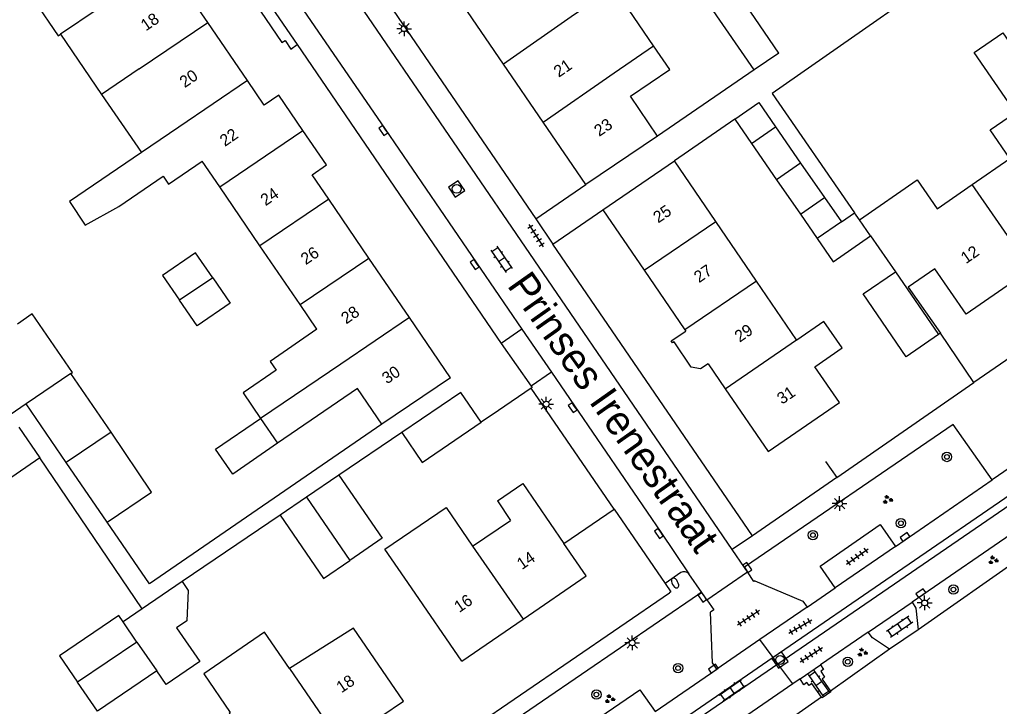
# Model space of a CAD drawing. Extents: x 137999 to 141000, y 397500 to 400501.
# Drawn here: x 138055 to 138138.3, y 399810.1 to 399868.5 of the extents above; entities that cross this region are included whole.
import ezdxf

# ---------------------------------------------------------------- set-up
doc = ezdxf.new("R2010")
doc.units = 0
for name, color, linetype in [('gg-afsc-erfafscheiding', 7, 'Continuous'), ('gg-afsc-muur', 7, 'Continuous'), ('gg-anno-huisnummerreeks BGT', 7, 'Continuous'), ('gg-anno-openbare ruimte label', 7, 'Continuous'), ('gg-bbg-bijgebouw', 7, 'Continuous'), ('gg-bbg-gedigitaliseerde bebouwing', 7, 'Continuous'), ('gg-bbg-gedigitaliseerde bijgebouw', 7, 'Continuous'), ('gg-bbg-hoofdgebouw', 7, 'Continuous'), ('gg-bbg-luifel en loopbrug', 7, 'Continuous'), ('gg-bbg-tussenscheiding', 7, 'Continuous'), ('gg-knt-verharding', 7, 'Continuous'), ('gg-knt-verharding nz', 7, 'Continuous'), ('gt-grn-weggrens', 7, 'Continuous'), ('gt-symb-boom', 7, 'Continuous'), ('gt-symb-brandkraan', 7, 'Continuous'), ('gt-symb-groenvak', 7, 'Continuous'), ('gt-symb-klinker verharding', 7, 'Continuous'), ('gt-symb-kolk', 7, 'Continuous'), ('gt-symb-lichtmast', 7, 'Continuous'), ('gt-symb-rioolschacht', 7, 'Continuous'), ('gt-symb-tegel verharding', 7, 'Continuous')]:
    doc.layers.add(name, color=color, linetype=linetype)

# ---------------------------------------------------------------- blocks, each defined once
blk = doc.blocks.new('gt0-KL1')
at = {"layer": 'gt-symb-klinker verharding'}
for p, q in [((-1.15, 0.3), (1.15, 0.3)), ((-1, -0.3), (-1, 0.3)), ((-0.5, 0.3), (-0.5, 0.45)), ((0, -0.3), (0, 0.3)), ((0.5, 0.3), (0.5, 0.45)), ((1, -0.3), (1, 0.3)), ((-1.15, -0.3), (1.15, -0.3)), ((-0.5, -0.45), (-0.5, -0.3)), ((0.5, -0.45), (0.5, -0.3))]:
    blk.add_line(p, q, dxfattribs=at)
blk = doc.blocks.new('gt0-KOLK')
at = {"layer": 'gt-symb-kolk'}
blk.add_lwpolyline([(0, 0), (0.375, 0), (0.375, 0.4), (-0.375, 0.4), (-0.375, 0), (0, 0)], dxfattribs=at)
blk = doc.blocks.new('gt0-BOOM')
at = {"layer": 'gt-symb-boom'}
for radius in [0.4, 0.2]:
    blk.add_circle((0, 0), radius, dxfattribs=at)
blk = doc.blocks.new('gt0-RS')
at = {"layer": 'gt-symb-rioolschacht'}
blk.add_lwpolyline([(-0.5, -0.5), (0.5, -0.5), (0.5, 0.5), (-0.5, 0.5)], close=True, dxfattribs=at)
blk.add_circle((0, 0), 0.375, dxfattribs=at)
blk = doc.blocks.new('gt0-TEG1')
at = {"layer": 'gt-symb-tegel verharding'}
for p, q in [((-1.125, 0), (1.125, 0)), ((-0.9, -0.25), (-0.9, 0.25)), ((-0.45, -0.25), (-0.45, 0.25)), ((0, -0.25), (0, 0.25)), ((0.45, -0.25), (0.45, 0.25)), ((0.9, -0.25), (0.9, 0.25))]:
    blk.add_line(p, q, dxfattribs=at)
blk = doc.blocks.new('gt0-GRVAK')
at = {"layer": 'gt-symb-groenvak'}
for p, q in [((-0.11, 0.189), (-0.228, 0.24)), ((-0.182, 0.153), (0.088, 0.153)), ((-0.091, 0.211), (-0.156, 0.322)), ((-0.047, 0.214), (-0.047, 0.393)), ((-0.004, 0.211), (0.061, 0.322)), ((0.015, 0.189), (0.133, 0.24)), ((0.262, -0.052), (0.197, 0.059)), ((0.305, -0.049), (0.305, 0.13)), ((0.349, -0.052), (0.414, 0.059)), ((-0.245, -0.228), (-0.363, -0.177)), ((-0.318, -0.264), (-0.047, -0.264)), ((-0.226, -0.206), (-0.291, -0.095)), ((-0.183, -0.203), (-0.183, -0.024)), ((-0.139, -0.206), (-0.074, -0.095)), ((-0.12, -0.228), (-0.002, -0.177)), ((0.243, -0.074), (0.125, -0.023)), ((0.17, -0.11), (0.441, -0.11)), ((0.368, -0.074), (0.486, -0.023))]:
    blk.add_line(p, q, dxfattribs=at)
blk = doc.blocks.new('gt0-LMAST')
at = {"layer": 'gt-symb-lichtmast'}
for p, q in [((-0.182, 0.173), (-0.447, 0.438)), ((-0.005, 0.246), (-0.005, 0.621)), ((0.172, 0.173), (0.437, 0.438)), ((-0.255, -0.004), (-0.63, -0.004)), ((-0.182, -0.181), (-0.447, -0.446)), ((-0.005, -0.254), (-0.005, -0.629)), ((0.437, -0.446), (0.172, -0.181)), ((0.245, -0.004), (0.62, -0.004))]:
    blk.add_line(p, q, dxfattribs=at)
blk.add_circle((-0.005, -0.004), 0.25, dxfattribs=at)
blk = doc.blocks.new('gt0-BR')
at = {"layer": 'gt-symb-brandkraan'}
for centre, radius, start, end in [((-0.244, 0), 0.206, 107.56694, 252.43307), ((0.599, -2.664), 3, 106.89205, 107.56694), ((0, -0.691), 0.938, 73.10799, 106.89205), ((-0.599, -2.664), 3, 72.43309, 73.10799), ((0.244, 0), 0.206, 287.56695, 72.43309), ((0.599, 2.664), 3, 252.43307, 253.10797), ((0, 0.691), 0.938, 253.10797, 286.89206), ((-0.599, 2.664), 3, 286.89206, 287.56695)]:
    blk.add_arc(centre, radius, start, end, dxfattribs=at)

msp = doc.modelspace()

# ---------------------------------------------------------------- linework, layer by layer
at = {"layer": 'gg-afsc-erfafscheiding'}
for p, q in [((138095.747, 399835.23), (138094.268, 399834.222)), ((138087.523, 399833.339), (138082.171, 399829.72)), ((138065.463, 399818.364), (138056.772, 399831.202)), ((138147.857, 399828.129), (138131.391, 399816.568)), ((138077.181, 399826.329), (138068.857, 399820.671)), ((138128.967, 399814.919), (138123.938, 399811.369))]:
    msp.add_line(p, q, dxfattribs=at)
for points in [[(138137.989, 399875.474), (138118.988, 399862.166), (138125.991, 399852.029)], [(138085.829, 399834.047), (138066.081, 399820.493), (138062.488, 399825.728)], [(138123.19, 399810.846), (138110.856, 399802.204), (138129.838, 399773.855)]]:
    msp.add_lwpolyline(points, dxfattribs=at)
at = {"layer": 'gg-afsc-muur'}
for p, q in [((138117.464, 399864.178), (138109.256, 399858.554)), ((138115.809, 399859.981), (138110.68, 399856.441)), ((138136.135, 399837.595), (138133.3, 399841.79)), ((138098.518, 399837.118), (138095.747, 399835.23)), ((138105.58, 399826.833), (138098.518, 399837.118)), ((138124.498, 399829.524), (138136.135, 399837.595)), ((138123.535, 399830.877), (138124.498, 399829.524)), ((138101.302, 399823.917), (138105.58, 399826.833))]:
    msp.add_line(p, q, dxfattribs=at)
at = {"layer": 'gg-bbg-bijgebouw'}
for p, q in [((138119.558, 399865.612), (138117.464, 399864.178)), ((138115.809, 399859.981), (138117.866, 399861.392)), ((138133.133, 399841.676), (138130.37, 399839.79))]:
    msp.add_line(p, q, dxfattribs=at)
for points in [[(138094.268, 399834.222), (138092.535, 399836.761), (138087.523, 399833.339)], [(138087.523, 399833.339), (138089.254, 399830.804), (138094.268, 399834.222)]]:
    msp.add_lwpolyline(points, dxfattribs=at)
at = {"layer": 'gg-bbg-gedigitaliseerde bebouwing'}
for p, q in [((138058.508, 399867.203), (138062.011, 399862.099)), ((138062.011, 399862.099), (138065.406, 399857.153)), ((138109.256, 399858.554), (138106.946, 399861.936)), ((138072.05, 399854.233), (138070.551, 399856.43)), ((138114.204, 399851.275), (138110.68, 399856.441)), ((138075.466, 399849.228), (138072.05, 399854.233)), ((138117.664, 399846.204), (138114.204, 399851.275)), ((138078.879, 399844.228), (138075.466, 399849.228)), ((138121.057, 399841.231), (138117.664, 399846.204)), ((138080.313, 399842.128), (138078.879, 399844.228)), ((138123.39, 399842.78), (138121.078, 399841.2)), ((138121.078, 399841.2), (138121.057, 399841.231)), ((138083.752, 399837.09), (138076.971, 399832.436)), ((138085.829, 399834.047), (138083.752, 399837.09)), ((138075.52, 399834.55), (138076.971, 399832.436)), ((138095.64, 399827.53), (138096.767, 399825.878)), ((138093.541, 399823.68), (138096.767, 399825.878)), ((138092.61, 399813.9), (138088.34, 399820.136)), ((138075.854, 399816.375), (138070.685, 399812.828)), ((138077.974, 399813.286), (138075.854, 399816.375)), ((138083.417, 399816.727), (138077.974, 399813.286))]:
    msp.add_line(p, q, dxfattribs=at)
for points in [[(138059.684, 399872.35), (138056.301, 399870.028), (138058.324, 399867.08), (138058.508, 399867.203)], [(138108.923, 399866.216), (138105.558, 399871.16), (138102.209, 399868.88)], [(138137.521, 399859.073), (138139.684, 399860.569), (138136.172, 399865.647), (138138.597, 399867.325), (138142.11, 399862.246)], [(138106.946, 399861.936), (138110.288, 399864.211), (138108.923, 399866.216)], [(138135.986, 399854.428), (138139.197, 399856.649), (138137.521, 399859.073)], [(138065.406, 399857.153), (138059.269, 399852.977), (138060.623, 399850.988), (138063.473, 399852.57), (138067.229, 399855.148), (138067.695, 399854.47), (138070.551, 399856.43)], [(138126.408, 399851.426), (138131.313, 399854.818), (138133.007, 399852.368), (138135.986, 399854.428)], [(138080.313, 399842.128), (138076.337, 399839.399), (138076.846, 399838.658), (138074.028, 399836.724), (138075.52, 399834.55)], [(138088.34, 399820.136), (138086.084, 399823.431), (138091.278, 399826.986), (138093.541, 399823.68)]]:
    msp.add_lwpolyline(points, dxfattribs=at)
at = {"layer": 'gg-bbg-gedigitaliseerde bijgebouw'}
for p, q in [((138119.558, 399865.612), (138115.845, 399871.05)), ((138117.464, 399864.178), (138113.727, 399869.583)), ((138117.866, 399861.392), (138119.282, 399859.344)), ((138115.809, 399859.981), (138117.231, 399857.925)), ((138117.231, 399857.925), (138119.282, 399859.344)), ((138121.39, 399851.911), (138123.441, 399853.329)), ((138123.441, 399853.329), (138124.874, 399851.256)), ((138121.39, 399851.911), (138122.812, 399849.855)), ((138124.874, 399851.256), (138125.991, 399852.029)), ((138126.408, 399851.426), (138125.991, 399852.029)), ((138127.358, 399850.059), (138129.468, 399847.008)), ((138062.818, 399833.373), (138059.407, 399838.361)), ((138055.593, 399835.775), (138054.249, 399834.865)), ((138059.008, 399830.798), (138055.593, 399835.775)), ((138054.971, 399833.803), (138056.772, 399831.202)), ((138062.488, 399825.728), (138059.008, 399830.798)), ((138082.171, 399829.72), (138079.422, 399827.852)), ((138079.422, 399827.852), (138077.181, 399826.329)), ((138068.857, 399820.671), (138065.463, 399818.364)), ((138065.463, 399818.364), (138063.836, 399817.258))]:
    msp.add_line(p, q, dxfattribs=at)
for points in [[(138122.812, 399849.855), (138124.187, 399847.866), (138127.358, 399850.059)], [(138071.455, 399846.513), (138070.001, 399848.631), (138067.183, 399846.697), (138068.624, 399844.596)], [(138130.37, 399839.79), (138126.722, 399845.133), (138129.468, 399847.008)], [(138071.455, 399846.513), (138072.944, 399844.343), (138070.126, 399842.409), (138068.624, 399844.596)], [(138059.407, 399838.361), (138059.537, 399838.451), (138056.123, 399843.425), (138054.868, 399842.563)], [(138062.488, 399825.728), (138066.264, 399828.284), (138062.818, 399833.373)], [(138056.772, 399831.202), (138051.878, 399827.843), (138050.096, 399830.438)], [(138082.171, 399829.72), (138085.854, 399824.355), (138083.098, 399822.464)], [(138077.181, 399826.329), (138080.879, 399820.941), (138083.098, 399822.464)], [(138068.857, 399820.671), (138069.366, 399819.929), (138069.246, 399817.333), (138068.387, 399816.744), (138070.349, 399813.884), (138067.49, 399811.922), (138066.697, 399813.077)], [(138063.836, 399817.258), (138063.478, 399817.784), (138058.447, 399814.365), (138059.964, 399812.132)], [(138066.697, 399813.077), (138061.653, 399809.648), (138059.964, 399812.132)]]:
    msp.add_lwpolyline(points, dxfattribs=at)
at = {"layer": 'gg-bbg-hoofdgebouw'}
for p, q in [((138071.039, 399868.2), (138067.562, 399873.288)), ((138096.167, 399864.666), (138092.743, 399869.689)), ((138074.403, 399863.277), (138071.039, 399868.2)), ((138099.522, 399859.743), (138096.167, 399864.666)), ((138103.15, 399854.42), (138099.522, 399859.743)), ((138109.256, 399858.554), (138103.15, 399854.42)), ((138104.6, 399852.29), (138110.68, 399856.441)), ((138084.724, 399848.179), (138081.314, 399853.187)), ((138104.6, 399852.29), (138108.111, 399847.15)), ((138088.171, 399843.116), (138084.724, 399848.179)), ((138108.111, 399847.15), (138111.581, 399842.07)), ((138091.653, 399838.002), (138088.171, 399843.116)), ((138111.581, 399842.07), (138111.647, 399841.974)), ((138133.3, 399841.79), (138133.133, 399841.676)), ((138113.546, 399839.192), (138114.991, 399837.076)), ((138091.653, 399838.002), (138085.829, 399834.047)), ((138092.61, 399813.9), (138097.825, 399817.47))]:
    msp.add_line(p, q, dxfattribs=at)
for points in [[(138079.122, 399859.032), (138077.073, 399862.028), (138075.835, 399861.181), (138074.403, 399863.277)], [(138081.314, 399853.187), (138079.897, 399855.269), (138081.13, 399856.097), (138079.122, 399859.032)], [(138140.985, 399847.215), (138135.48, 399843.41), (138132.81, 399847.27), (138130.54, 399845.7), (138133.3, 399841.79)], [(138114.991, 399837.076), (138118.65, 399831.72), (138124.72, 399835.91), (138122.63, 399838.94), (138124.94, 399840.54), (138123.39, 399842.78)], [(138113.546, 399839.192), (138112.9, 399838.764), (138112.109, 399838.915), (138110.656, 399841.053), (138110.525, 399840.966), (138110.414, 399841.132), (138111.647, 399841.974)], [(138095.64, 399827.53), (138097.81, 399829.01), (138101.302, 399823.917)], [(138097.825, 399817.47), (138103.2, 399821.15), (138101.302, 399823.917)], [(138083.3, 399805.898), (138086.089, 399807.791), (138086.229, 399808.508), (138085.807, 399809.121), (138085.888, 399809.177), (138085.832, 399809.26), (138087.654, 399810.514), (138083.417, 399816.727)], [(138070.685, 399812.828), (138072.942, 399809.553), (138072.848, 399809.488), (138077.091, 399803.32)]]:
    msp.add_lwpolyline(points, dxfattribs=at)
at = {"layer": 'gg-bbg-luifel en loopbrug'}
for p, q in [((138119.282, 399859.344), (138121.414, 399856.261)), ((138117.231, 399857.925), (138119.363, 399854.842)), ((138121.414, 399856.261), (138119.363, 399854.842)), ((138121.414, 399856.261), (138123.441, 399853.329)), ((138119.363, 399854.842), (138121.39, 399851.911))]:
    msp.add_line(p, q, dxfattribs=at)
msp.add_lwpolyline([(138076.971, 399832.436), (138073.153, 399829.815), (138071.702, 399831.929), (138075.52, 399834.55)], dxfattribs=at)
at = {"layer": 'gg-bbg-tussenscheiding'}
for p, q in [((138061.723, 399869.363), (138058.508, 399867.203)), ((138102.209, 399868.88), (138096.167, 399864.666)), ((138065.207, 399864.259), (138071.039, 399868.2)), ((138105.579, 399863.939), (138108.923, 399866.216)), ((138065.207, 399864.259), (138062.011, 399862.099)), ((138099.522, 399859.743), (138105.579, 399863.939)), ((138074.403, 399863.277), (138068.581, 399859.315)), ((138068.581, 399859.315), (138065.406, 399857.153)), ((138072.05, 399854.233), (138079.122, 399859.032)), ((138140.985, 399847.215), (138135.986, 399854.428)), ((138081.314, 399853.187), (138075.466, 399849.228)), ((138108.111, 399847.15), (138114.204, 399851.275)), ((138124.874, 399851.256), (138122.812, 399849.855)), ((138127.358, 399850.059), (138126.408, 399851.426)), ((138078.879, 399844.228), (138084.724, 399848.179)), ((138129.468, 399847.008), (138133.133, 399841.676)), ((138071.455, 399846.513), (138068.624, 399844.596)), ((138117.664, 399846.204), (138111.581, 399842.07)), ((138088.171, 399843.116), (138082.336, 399839.165)), ((138114.991, 399837.076), (138121.057, 399841.231)), ((138082.336, 399839.165), (138075.52, 399834.55)), ((138059.407, 399838.361), (138055.593, 399835.775)), ((138062.818, 399833.373), (138059.008, 399830.798)), ((138079.422, 399827.852), (138083.098, 399822.464)), ((138093.541, 399823.68), (138097.825, 399817.47)), ((138065.016, 399815.534), (138063.836, 399817.258)), ((138065.016, 399815.534), (138059.964, 399812.132)), ((138065.016, 399815.534), (138066.697, 399813.077)), ((138077.974, 399813.286), (138083.163, 399805.707))]:
    msp.add_line(p, q, dxfattribs=at)
at = {"layer": 'gg-knt-verharding'}
for p, q in [((138242.972, 399899.292), (138119.076, 399814.219)), ((138119.47, 399813.69), (138243.348, 399898.735)), ((138077.925, 399882.236), (138098.899, 399851.507)), ((138115.599, 399823.393), (138080.112, 399875.351)), ((138185.501, 399871.719), (138136.135, 399837.595)), ((138078.631, 399866.334), (138095.965, 399840.915)), ((138098.899, 399851.507), (138103.15, 399854.42)), ((138100.35, 399849.362), (138104.6, 399852.29)), ((138117.328, 399824.553), (138100.35, 399849.362)), ((138095.965, 399840.915), (138098.522, 399837.276)), ((138142.764, 399832.816), (138137.675, 399829.318)), ((138124.498, 399829.524), (138117.328, 399824.553)), ((138129.462, 399823.659), (138137.675, 399829.318)), ((138145.709, 399829.12), (138130.882, 399818.915)), ((138105.58, 399826.833), (138109.895, 399820.518)), ((138129.462, 399823.659), (138124.337, 399820.154)), ((138116.633, 399821.879), (138115.599, 399823.393)), ((138116.633, 399821.879), (138116.726, 399821.944)), ((138116.888, 399821.514), (138116.633, 399821.879)), ((138111.243, 399821.439), (138109.895, 399820.518)), ((138113.003, 399819.752), (138111.905, 399821.331)), ((138113.444, 399819.118), (138116.888, 399821.514)), ((138053.848, 399781.16), (138110.281, 399819.72)), ((138112.746, 399819.573), (138096.159, 399808.243)), ((138112.746, 399819.573), (138113.003, 399819.752)), ((138113.444, 399819.118), (138113.003, 399819.752)), ((138121.954, 399818.51), (138124.337, 399820.154)), ((138121.954, 399818.51), (138117.946, 399815.739)), ((138127.164, 399816.365), (138130.882, 399818.915)), ((138127.164, 399816.365), (138123.093, 399813.601)), ((138131.391, 399816.568), (138128.967, 399814.919)), ((138117.946, 399815.739), (138114.304, 399813.22)), ((138119.076, 399814.219), (138059.432, 399773.265)), ((138059.8, 399772.726), (138119.47, 399813.69)), ((138121.36, 399812.397), (138123.093, 399813.601)), ((138109.055, 399809.641), (138114.304, 399813.22)), ((138120.745, 399811.975), (138109.827, 399804.495)), ((138121.36, 399812.397), (138120.745, 399811.975))]:
    msp.add_line(p, q, dxfattribs=at)
for points in [[(138074.594, 399870.536), (138077.336, 399866.5), (138077.615, 399866.677), (138078.105, 399865.95), (138078.631, 399866.334)], [(138098.522, 399837.276), (138098.595, 399837.172), (138098.518, 399837.118)], [(138137.675, 399829.318), (138134.361, 399834.022), (138116.726, 399821.944)], [(138124.337, 399820.154), (138123.064, 399821.984), (138128.174, 399825.531), (138129.462, 399823.659)], [(138117.521, 399820.734), (138117.449, 399820.685), (138116.888, 399821.514)], [(138109.895, 399820.518), (138110.39, 399819.794), (138110.281, 399819.72)], [(138117.521, 399820.734), (138121.607, 399819.005), (138121.954, 399818.51)], [(138113.444, 399819.118), (138114.035, 399818.269), (138113.743, 399818.066)], [(138130.882, 399818.915), (138131.21, 399818.408), (138131.391, 399816.568)], [(138114.304, 399813.22), (138113.934, 399813.766), (138113.743, 399818.066)], [(138128.967, 399814.919), (138127.51, 399815.881), (138127.164, 399816.365)], [(138123.093, 399813.601), (138123.36, 399813.206), (138123.129, 399813.057), (138123.454, 399812.536), (138123.229, 399812.379), (138123.938, 399811.369)], [(138123.19, 399810.846), (138122.357, 399812.003), (138122.126, 399811.846), (138121.946, 399812.086), (138121.686, 399811.91), (138121.36, 399812.397)], [(138103.944, 399806.129), (138102.641, 399807.976), (138107.757, 399811.472), (138109.055, 399809.641)], [(138123.938, 399811.369), (138123.987, 399811.299), (138123.229, 399810.792), (138123.19, 399810.846)]]:
    msp.add_lwpolyline(points, dxfattribs=at)
msp.add_arc((138111.512, 399821.004), 0.511, 39.71904, 121.74953, dxfattribs=at)
at = {"layer": 'gg-knt-verharding nz'}
for p, q in [((138075.387, 399871.075), (138078.631, 399866.334)), ((138097.734, 399842.121), (138095.965, 399840.915)), ((138097.734, 399842.121), (138100.228, 399838.477)), ((138100.228, 399838.477), (138098.522, 399837.276))]:
    msp.add_line(p, q, dxfattribs=at)
for points in [[(138076.658, 399872.94), (138086.115, 399859.134), (138097.734, 399842.121)], [(138100.228, 399838.477), (138109.524, 399824.866), (138111.905, 399821.331)]]:
    msp.add_lwpolyline(points, dxfattribs=at)
at = {"layer": 'gt-grn-weggrens'}
for p, q in [((138098.899, 399851.507), (138100.35, 399849.362)), ((138117.328, 399824.553), (138115.599, 399823.393)), ((138119.076, 399814.219), (138117.946, 399815.739)), ((138119.47, 399813.69), (138119.076, 399814.219)), ((138120.745, 399811.975), (138119.47, 399813.69))]:
    msp.add_line(p, q, dxfattribs=at)

# ---------------------------------------------------------------- block references
at = {"layer": 'gt-symb-boom'}
for p in [(138133.841, 399831.269), (138129.929, 399825.633), (138122.458, 399824.63), (138134.393, 399819.998), (138110.995, 399813.316), (138125.42, 399813.857), (138104.056, 399811.067)]:
    msp.add_blockref('gt0-BOOM', p, dxfattribs=at)
at = {"layer": 'gt-symb-brandkraan', "rotation": 118.37344876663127}
msp.add_blockref('gt0-BR', (138110.745, 399820.549), dxfattribs=at)
at = {"layer": 'gt-symb-groenvak'}
for p in [(138128.797, 399827.639), (138137.768, 399822.495), (138126.648, 399814.649), (138105.182, 399810.693)]:
    msp.add_blockref('gt0-GRVAK', p, dxfattribs=at)
at = {"layer": 'gt-symb-klinker verharding'}
for p, rotation in [((138095.988, 399848.07), -55.59476571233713), ((138129.817, 399816.822), -145.46787543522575), ((138122.949, 399812.001), -54.97512671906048), ((138115.604, 399811.432), 35.02487327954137)]:
    msp.add_blockref('gt0-KL1', p, dxfattribs=dict(at, rotation=rotation))
at = {"layer": 'gt-symb-kolk'}
for p, rotation in [((138086.115, 399859.134), 124.41750151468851), ((138093.877, 399847.755), 124.30112174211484), ((138102.202, 399835.573), 124.20262255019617), ((138109.524, 399824.866), 124.37052924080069), ((138130.393, 399824.307), 34.81835448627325), ((138116.721, 399821.753), -55.054255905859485), ((138113.209, 399819.456), 124.80692065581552), ((138131.749, 399819.521), 34.48490803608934), ((138114.107, 399813.112), 34.48490803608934)]:
    msp.add_blockref('gt0-KOLK', p, dxfattribs=dict(at, rotation=rotation))
at = {"layer": 'gt-symb-lichtmast'}
for p in [(138087.721, 399867.685), (138099.797, 399835.767), (138124.726, 399827.31), (138131.957, 399818.862), (138107.107, 399815.468)]:
    msp.add_blockref('gt0-LMAST', p, dxfattribs=at)
at = {"layer": 'gt-symb-rioolschacht'}
for p, rotation in [((138092.18, 399854.061), 124.12654292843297), ((138119.666, 399814.013), 34.81835448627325)]:
    msp.add_blockref('gt0-RS', p, dxfattribs=dict(at, rotation=rotation))
at = {"layer": 'gt-symb-tegel verharding'}
for p, rotation in [((138098.933, 399850.088), -57.454106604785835), ((138126.232, 399822.803), 35.10468688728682), ((138116.975, 399817.591), -146.21457204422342), ((138121.383, 399816.853), 30.59043540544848), ((138122.313, 399814.465), 32.70422579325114)]:
    msp.add_blockref('gt0-TEG1', p, dxfattribs=dict(at, rotation=rotation))

# ---------------------------------------------------------------- texts
at = {"layer": 'gg-anno-huisnummerreeks BGT'}
for s, rotation, p in [('18', 34.3, (138065.771, 399867.441)), ('21', 34.3, (138100.86, 399863.503)), ('20', 34.3, (138069.069, 399862.616)), ('23', 34.3, (138104.292, 399858.468)), ('22', 34.4, (138072.486, 399857.623)), ('24', 34.4, (138075.942, 399852.578)), ('25', 34.3, (138109.309, 399851.109)), ('26', 34.2, (138079.363, 399847.563)), ('12', 34.7, (138135.465, 399847.655)), ('27', 34.3, (138112.777, 399846.033)), ('28', 34.2, (138082.792, 399842.527)), ('29', 34.3, (138116.229, 399840.978)), ('30', 34.2, (138086.262, 399837.43)), ('31', 34.3, (138119.834, 399835.7)), ('14', 34.4, (138097.729, 399821.645)), ('16', 34.4, (138092.405, 399818)), ('18', 34.3, (138082.388, 399811.162))]:
    msp.add_text(s, height=1, rotation=rotation, dxfattribs=at).set_placement(p)
at = {"layer": 'gg-anno-openbare ruimte label'}
msp.add_text('Prinses Irenestraat', height=2.5, rotation=305.2, dxfattribs=at).set_placement((138096.41, 399845.847))

doc.saveas('drawing.dxf')
